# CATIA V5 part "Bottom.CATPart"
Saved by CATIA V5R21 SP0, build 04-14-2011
Part number: Fix_Base
Bounding box of the stored display mesh (mm): x -90 to 90, y -85 to 85, z 0 to 2.8
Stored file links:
  C:\Users\Pouria\Desktop\Box\Bottom.CATPart
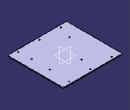
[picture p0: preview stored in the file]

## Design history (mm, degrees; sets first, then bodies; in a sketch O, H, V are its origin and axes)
Body1 (main body)
  Sketch1 on xy-plane, origin (0, 0, 0), H (1, 0, 0), V (0, 1, 0)
    line L1 (80, 70) -> (80, -70)
    line L2 (80, -70) -> (-80, -70)
    line L3 (-80, -70) -> (-80, 70)
    line L4 (-80, 70) -> (80, 70)
    line L5 (90, 85) -> (90, 40)
    line L6 (90, -85) -> (40, -85)
    line L7 (-90, -85) -> (-90, -40)
    line L8 (-90, 85) -> (-40, 85)
    line L9 (90, 40) -> (92.8, 40)
    line L10 (92.8, 40) -> (92.8, -40)
    line L11 (92.8, -40) -> (90, -40)
    point P12 (90, -40)
    point P13 (-90, 40)
    line L12 (-90, 40) -> (-92.8, 40)
    line L13 (-92.8, 40) -> (-92.8, -40)
    line L14 (-92.8, -40) -> (-90, -40)
    point P17 (40, 85)
    line L15 (40, 85) -> (40, 87.8)
    line L16 (40, 87.8) -> (-40, 87.8)
    line L17 (-40, 87.8) -> (-40, 85)
    line L18 (40, -85) -> (40, -87.8)
    line L19 (40, -87.8) -> (-40, -87.8)
    line L20 (-40, -87.8) -> (-40, -85)
    point P24 (-40, -85)
    line L21 (90, -40) -> (90, -85)
    line L22 (40, 85) -> (90, 85)
    line L23 (-90, 40) -> (-90, 85)
    line L24 (-40, -85) -> (-90, -85)
    circle A1 centre (0, 77.5) radius 1.9
    point P25 (0, 77.5)
    circle A2 centre (0, -77.5) radius 1.9
    point P26 (0, -77.5)
    circle A3 centre (65, 77.5) radius 1.9
    point P27 (65, 77.5)
    circle A4 centre (-65, 77.5) radius 1.9
    point P28 (-65, 77.5)
    circle A5 centre (-65, -77.5) radius 1.9
    point P29 (-65, -77.5)
    circle A6 centre (-45, -77.5) radius 1.5
    point P30 (-45, -77.5)
    circle A7 centre (45, -77.5) radius 1.5
    point P31 (45, -77.5)
    circle A8 centre (65, -77.5) radius 1.9
    point P32 (65, -77.5)
    circle A9 centre (45, 77.5) radius 1.5
    point P33 (45, 77.5)
    circle A10 centre (-45, 77.5) radius 1.5
    point P34 (-45, 77.5)
    distance L1 L5 = 10
    distance L2 L6 = 15
    distance L1 L3 = 160
    distance L4 L2 = 140
    length L11 = 2.8
    length L15 = 2.8
    length L10 = 80
    length L16 = 80
    distance P25 L4 = 7.5
    distance P33 L4 = 7.5
    distance P27 L4 = 7.5
    distance P34 L4 = 7.5
    distance P28 L4 = 7.5
    distance P29 L2 = 7.5
    distance P30 L2 = 7.5
    distance P26 L2 = 7.5
    distance P31 L2 = 7.5
    distance P32 L2 = 7.5
    distance P32 L21 = 25
    distance P29 L7 = 25
    distance P27 L5 = 25
    distance P28 L23 = 25
    radius A3 = 1.9
    radius A4 = 1.9
    radius A1 = 1.9
    radius A8 = 1.9
    radius A2 = 1.9
    radius A5 = 1.9
    distance P33 L5 = 45
    distance P34 L23 = 45
    distance P31 L21 = 45
    distance P30 L7 = 45
    radius A7 = 1.5
    radius A6 = 1.5
    radius A9 = 1.5
    radius A10 = 1.5
    vertical: L1 V, L3 V, L5 V, L7 V, L10 V, L13 V, L15 V, L17 V, L18 V, L20 V, L21 V, L23 V
    horizontal: L2 H, L4 H, L6 H, L8 H, L9 H, L11 H, L12 H, L14 H, L16 H, L19 H, L22 H, L24 H
    equidistance: L1 L3 O, L2 L4 O, L5 L7 O, L6 L8 O
    coincidence: P12 L5, P13 L7, P17 L8, P24 L6, L18 L15, L20 L17, L11 L14, L9 L12, L5 L21, L8 L22, L7 L23, L6 L24, P25 V, P26 V
    symmetry: L10 L13 V, L19 L16 H, L15 L17 V, L18 L20 V, L11 L9 H, L14 L12 H
  Pad1: profile Sketch1, direction (0, 0, 1), length 2.8
  Fillet1: radius 10, on edge [face of Pad1 from Sketch1.L4 | face of Pad1 from Sketch1.L3]; edge [face of Pad1 from Sketch1.L1 | face of Pad1 from Sketch1.L4]; edge [face of Pad1 from Sketch1.L2 | face of Pad1 from Sketch1.L1]; edge [face of Pad1 from Sketch1.L3 | face of Pad1 from Sketch1.L2]
  Sketch2 on end face of Pad1, origin (0, 0, 2.8), H (1, 0, 0), V (0, 1, 0)
    line L1 (101.4426, 49.6819) -> (90, 49.6819)
    line L2 (90, 49.6819) -> (90, -51.9452)
    line L3 (90, -51.9452) -> (101.4426, -51.9452)
    line L4 (101.4426, -51.9452) -> (101.4426, 49.6819)
    line L5 (-45.6857, 92.692) -> (55.6289, 92.692)
    line L6 (55.6289, 92.692) -> (55.6289, 85)
    line L7 (55.6289, 85) -> (-45.6857, 85)
    line L8 (-45.6857, 85) -> (-45.6857, 92.692)
    line L9 (-112.17, 48.0503) -> (-90, 48.0503)
    line L10 (-90, 48.0503) -> (-90, -46.351)
    line L11 (-90, -46.351) -> (-112.17, -46.351)
    line L12 (-112.17, -46.351) -> (-112.17, 48.0503)
    line L13 (-47.757, -92.9251) -> (52.604, -92.9251)
    line L14 (52.604, -92.9251) -> (52.604, -85)
    line L15 (52.604, -85) -> (-47.757, -85)
    line L16 (-47.757, -85) -> (-47.757, -92.9251)
    reference projected line E1 (40, -85) -> (90, -85) from edge [face of Pad1 from Sketch1.L6 | end face of Pad1]
    reference projected line E2 (90, -85) -> (90, -40) from edge [face of Pad1 from Sketch1.L21 | end face of Pad1]
    reference projected line E3 (90, 85) -> (40, 85) from edge [face of Pad1 from Sketch1.L22 | end face of Pad1]
    reference projected line E4 (-90, -40) -> (-90, -85) from edge [face of Pad1 from Sketch1.L7 | end face of Pad1]
    horizontal: L1 H, L3 H, L5 H, L7 H, L9 H, L11 H, L13 H, L15 H
    vertical: L2 V, L4 V, L6 V, L8 V, L10 V, L12 V, L14 V, L16 V
    coincidence: L15 E1, L2 E2, L7 E3, L10 E4
  Pocket1: profile Sketch2, direction (0, 0, -1), up to start face of Pad1
  Sketch3 on end face of Pad1, origin (0, 0, 2.8), H (1, 0, 0), V (0, 1, 0)
    circle A1 centre (-12.5, 38.75) radius 1.75
    point P1 (-12.5, 38.75)
    circle A2 centre (62.5, 16.25) radius 1.75
    point P2 (62.5, 16.25)
    circle A3 centre (62.5, -38.75) radius 1.75
    point P3 (62.5, -38.75)
    circle A4 centre (-52.5, -38.75) radius 1.75
    point P4 (-52.5, -38.75)
    line L1 (88, 83) -> (88, -83)
    line L2 (88, -83) -> (-88, -83)
    line L3 (-88, -83) -> (-88, 83)
    line L4 (-88, 83) -> (88, 83)
    reference projected line E1 (40, 85) -> (90, 85) from edge [face of Pad1 | end face of Pad1]
    reference projected line E3 (90, 85) -> (90, 40) from edge [face of Pad1 | end face of Pad1]
    circle A5 centre (65, -77.5) radius 2.5
    circle A6 centre (0, -77.5) radius 2.5
    circle A7 centre (-65, -77.5) radius 2.5
    circle A8 centre (-65, 77.5) radius 2.5
    circle A9 centre (0, 77.5) radius 2.5
    circle A10 centre (65, 77.5) radius 2.5
    reference projected circle E5 centre (65, 77.5) radius 1.9 from edge [end face of Pad1 | face of Pad1 from Sketch1.A3]
    reference projected circle E6 centre (0, 77.5) radius 1.9 from edge [end face of Pad1 | face of Pad1 from Sketch1.A1]
    reference projected circle E7 centre (-65, 77.5) radius 1.9 from edge [end face of Pad1 | face of Pad1 from Sketch1.A4]
    reference projected circle E8 centre (65, -77.5) radius 1.9 from edge [end face of Pad1 | face of Pad1 from Sketch1.A8]
    reference projected circle E9 centre (0, -77.5) radius 1.9 from edge [end face of Pad1 | face of Pad1 from Sketch1.A2]
    reference projected circle E10 centre (-65, -77.5) radius 1.9 from edge [end face of Pad1 | face of Pad1 from Sketch1.A5]
    radius A1 = 1.75
    radius A2 = 1.75
    radius A3 = 1.75
    radius A4 = 1.75
    distance P2 V = 62.5
    distance P2 H = 16.25
    distance P1 V = 12.5
    distance P1 H = 38.75
    distance P4 V = 52.5
    distance P4 H = 38.75
    distance P3 V = 62.5
    distance P3 H = 38.75
    distance L4 E1 = 2
    distance L1 E3 = 2
    radius A5 = 2.5
    radius A6 = 2.5
    radius A7 = 2.5
    radius A10 = 2.5
    radius A9 = 2.5
    radius A8 = 2.5
    vertical: L1 V, L3 V
    horizontal: L2 H, L4 H
    equidistance: L1 L3 O, L2 L4 O
    concentricity: A10 E5, A9 E6, A8 E7, A5 E8, A6 E9, A7 E10
  Pad2: profile Sketch3, direction (0, 0, 1), up to start face of Pad1
  Fillet2: radius 5, on edge [face of Pad1 | face of Pad1] (x4)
